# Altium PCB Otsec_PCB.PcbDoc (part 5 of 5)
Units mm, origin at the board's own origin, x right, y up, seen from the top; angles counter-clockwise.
Board outline 170 x 120 mm, 3 copper layers (Top Layer, Internal Plane 1, Bottom Layer), stack 1.608 mm thick; 1624 components, 0 nets, 5478 pads, 0 vias.
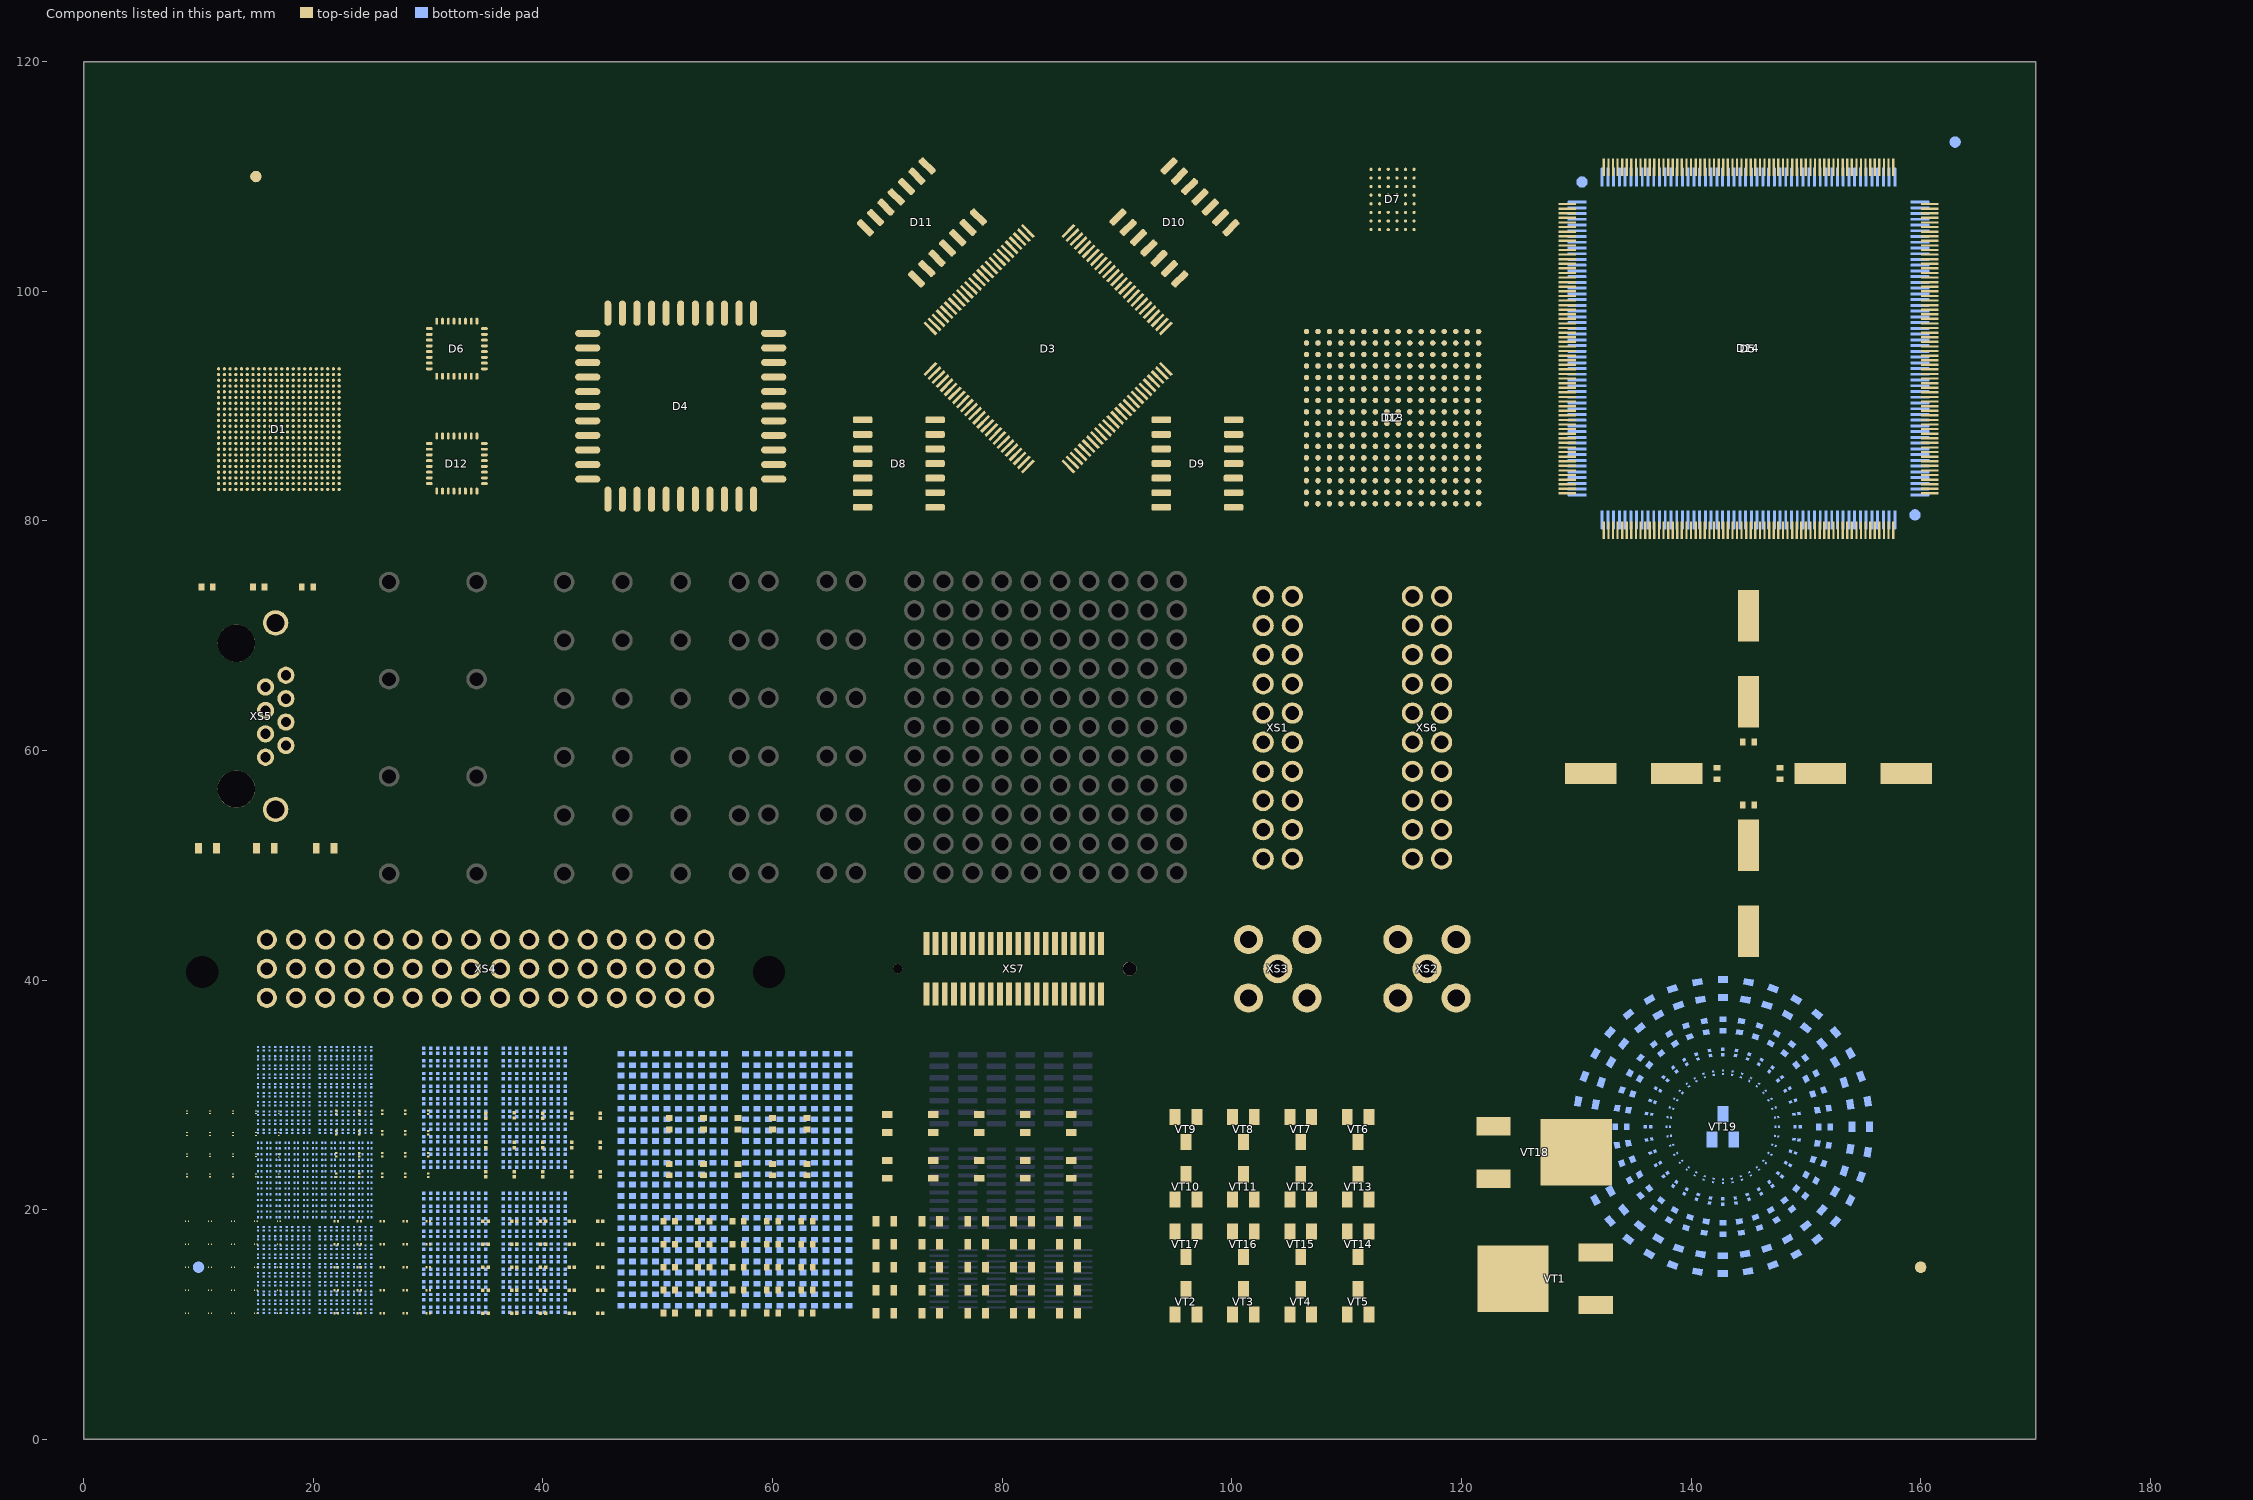
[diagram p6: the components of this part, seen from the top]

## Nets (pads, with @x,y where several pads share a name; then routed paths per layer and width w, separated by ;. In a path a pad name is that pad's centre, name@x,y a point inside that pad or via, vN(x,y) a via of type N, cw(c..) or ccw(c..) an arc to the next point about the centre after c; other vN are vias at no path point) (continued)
copper on no net: | length 2663.3
  Top Layer w0.051: 26.98,107.465 28.149,107.465 ; 26.98,107.516 27.996,107.516 ; 26.98,107.567 27.895,107.567 ; 26.98,107.618 27.793,107.618 ; 26.98,107.668 27.742,107.668 ; 26.98,107.719 27.641,107.719 ; 27.031,107.364 28.453,107.364 ; 27.031,107.414 28.301,107.414 ; 27.031,107.77 27.742,107.77 ; 27.031,107.821 27.844,107.821 ; 27.082,107.262 28.86,107.262 ; 27.082,107.313 28.606,107.313 ; 27.082,107.872 27.945,107.872 ; 27.133,107.211 29.063,107.211 ; 27.133,107.922 28.047,107.922 ; 27.183,107.16 29.317,107.16 ; 27.183,107.973 28.149,107.973 ; 27.234,107.11 30.028,107.11 ; 27.234,108.024 28.301,108.024 ; 27.285,107.059 30.028,107.059 ; 27.336,107.008 30.485,107.008 ; 27.336,108.075 28.453,108.075 ; 27.387,108.126 28.606,108.126 ; 27.437,106.957 31.095,106.957 ; 27.488,106.906 36.48,106.906 ; 27.488,108.176 28.809,108.176 ; 27.59,106.856 36.48,106.856 ; 27.59,108.227 29.012,108.227 ; 27.691,106.805 36.429,106.805 ; 27.742,108.278 29.215,108.278 ; 27.793,106.754 36.429,106.754 ; 27.895,106.703 36.378,106.703 ; 27.895,108.329 29.52,108.329 ; 27.996,106.652 36.327,106.652 ; 28.047,108.38 29.825,108.38 ; 28.149,106.602 36.277,106.602 ; 28.199,108.43 30.181,108.43 ; 28.301,106.551 36.226,106.551 ; 28.453,106.5 36.124,106.5 ; 28.453,108.481 30.689,108.481 ; 28.606,106.449 36.023,106.449 ; 28.657,108.532 31.4,108.532 ; 28.809,106.398 35.921,106.398 ; 28.911,108.583 36.327,108.583 ; 29.012,106.348 35.819,106.348 ; 29.215,106.246 35.464,106.246 ; 29.215,106.297 35.667,106.297 ; 29.215,108.634 36.023,108.634 ; 29.266,106.094 29.723,106.094 ; 29.266,106.144 29.673,106.144 ; 29.266,106.195 29.673,106.195 ; 29.317,105.992 29.774,105.992 ; 29.317,106.043 29.723,106.043 ; 29.368,105.89 29.876,105.89 ; 29.368,105.941 29.825,105.941 ; 29.368,107.16 30.181,107.16 ; 29.419,105.789 29.927,105.789 ; 29.419,105.84 29.876,105.84 ; 29.419,107.211 30.333,107.211 ; 29.469,105.738 29.977,105.738 ; 29.52,105.687 30.028,105.687 ; 29.52,107.262 30.536,107.262 ; 29.571,105.586 30.181,105.586 ; 29.571,105.636 30.13,105.636 ; 29.571,108.684 35.667,108.684 ; 29.622,105.535 30.231,105.535 ; 29.622,107.313 30.739,107.313 ; 29.673,105.484 30.333,105.484 ; 29.723,105.433 30.435,105.433 ; 29.723,107.364 30.993,107.364 ; 29.774,105.382 30.536,105.382 ; 29.825,105.332 30.638,105.332 ; 29.825,106.195 35.21,106.195 ; 29.876,105.281 30.79,105.281 ; 29.876,107.414 31.349,107.414 ; 29.927,105.23 31.4,105.23 ; 30.028,105.179 31.298,105.179 ; 30.028,107.465 31.857,107.465 ; 30.028,108.735 35.21,108.735 ; 30.079,105.128 31.298,105.128 ; 30.13,105.078 31.603,105.078 ; 30.181,106.144 34.956,106.144 ; 30.181,111.275 31.044,111.275 ; 30.181,111.326 30.841,111.326 ; 30.181,111.377 30.587,111.377 ; 30.231,105.027 32.06,105.027 ; 30.231,107.516 35.819,107.516 ; 30.231,111.224 31.197,111.224 ; 30.282,104.976 34.854,104.976 ; 30.282,111.174 31.349,111.174 ; 30.333,111.123 31.501,111.123 ; 30.384,104.925 34.803,104.925 ; 30.435,107.567 35.616,107.567 ; 30.435,111.072 31.603,111.072 ; 30.485,104.874 34.803,104.874 ; 30.485,111.021 31.705,111.021 ; 30.536,108.786 34.702,108.786 ; 30.536,110.97 31.755,110.97 ; 30.587,104.824 34.753,104.824 ; 30.587,110.92 31.857,110.92 ; 30.638,104.773 34.702,104.773 ; 30.638,106.094 34.549,106.094 ; 30.638,107.618 35.413,107.618 ; 30.638,110.869 31.908,110.869 ; 30.739,110.818 31.959,110.818 ; 30.79,104.722 34.651,104.722 ; 30.79,110.767 32.009,110.767 ; 30.841,104.671 34.6,104.671 ; 30.841,110.716 32.06,110.716 ; 30.892,104.57 34.346,104.57 ; 30.892,104.62 34.499,104.62 ; 30.892,105.281 31.552,105.281 ; 30.892,110.666 32.111,110.666 ; 30.943,104.519 34.194,104.519 ; 30.943,107.668 35.057,107.668 ; 30.943,110.615 32.111,110.615 ; 30.993,104.468 31.451,104.468 ; 30.993,105.332 31.654,105.332 ; 31.044,104.417 31.501,104.417 ; 31.044,105.382 31.857,105.382 ; 31.044,110.564 32.162,110.564 ; 31.095,104.366 31.552,104.366 ; 31.095,110.513 32.162,110.513 ; 31.146,104.316 31.654,104.316 ; 31.146,105.433 32.111,105.433 ; 31.146,110.462 32.213,110.462 ; 31.197,104.265 31.705,104.265 ; 31.197,110.412 32.213,110.412 ; 31.247,106.043 34.041,106.043 ; 31.247,110.361 32.263,110.361 ; 31.298,104.214 31.755,104.214 ; 31.298,105.484 34.549,105.484 ; 31.298,107.719 34.651,107.719 ; 31.298,108.837 33.94,108.837 ; 31.298,110.31 32.263,110.31 ; 31.349,104.163 31.857,104.163 ; 31.4,104.112 31.908,104.112 ; 31.4,110.259 32.263,110.259 ; 31.451,105.535 34.448,105.535 ; 31.451,110.208 32.263,110.208 ; 31.501,104.062 31.959,104.062 ; 31.501,110.158 32.314,110.158 ; 31.552,104.011 32.06,104.011 ; 31.552,104.468 34.041,104.468 ; 31.552,110.107 32.314,110.107 ; 31.603,105.586 34.295,105.586 ; 31.603,110.056 32.314,110.056 ; 31.654,103.96 32.111,103.96 ; 31.654,110.005 32.314,110.005 ; 31.705,103.909 32.162,103.909 ; 31.705,109.954 32.314,109.954 ; 31.755,103.858 32.213,103.858 ; 31.755,109.904 32.314,109.904 ; 31.806,104.417 33.737,104.417 ; 31.806,105.636 34.041,105.636 ; 31.806,109.853 32.314,109.853 ; 31.857,103.808 32.263,103.808 ; 31.857,107.77 33.889,107.77 ; 31.857,109.802 32.314,109.802 ; 31.908,103.757 32.314,103.757 ; 31.908,109.751 32.314,109.751 ; 31.959,103.706 32.365,103.706 ; 31.959,109.7 32.365,109.7 ; 32.009,103.655 32.416,103.655 ; 32.009,109.65 32.365,109.65 ; 32.06,103.604 32.721,103.604 ; 32.111,103.554 32.721,103.554 ; 32.111,109.599 32.365,109.599 ; 32.162,103.503 32.721,103.503 ; 32.162,105.687 33.635,105.687 ; 32.162,109.548 32.365,109.548 ; 32.213,103.452 32.721,103.452 ; 32.213,104.366 33.279,104.366 ; 32.213,109.446 32.365,109.446 ; 32.213,109.497 32.365,109.497 ; 32.263,103.401 32.721,103.401 ; 32.263,109.396 32.365,109.396 ; 32.314,103.3 32.721,103.3 ; 32.314,103.35 32.721,103.35 ; 32.365,103.198 32.721,103.198 ; 32.365,103.249 32.721,103.249 ; 32.416,103.046 32.721,103.046 ; 32.416,103.096 32.721,103.096 ; 32.416,103.147 32.721,103.147 ; 32.467,102.842 32.721,102.842 ; 32.467,102.893 32.721,102.893 ; 32.467,102.944 32.721,102.944 ; 32.467,102.995 32.721,102.995 ; 32.467,103.655 32.721,103.655 ; 32.467,103.706 32.721,103.706 ; 32.467,103.757 32.721,103.757 ; 32.467,103.808 32.721,103.808 ; 32.467,103.858 32.721,103.858 ; 32.467,103.909 32.721,103.909 ; 32.467,103.96 32.721,103.96 ; 32.467,104.011 32.721,104.011 ; 32.467,104.062 32.721,104.062 ; 32.467,104.112 32.721,104.112 ; 32.467,104.163 32.721,104.163 ; 32.467,104.214 32.721,104.214 ; 32.467,104.265 32.721,104.265 ; 32.467,104.316 32.721,104.316 ; 32.467,105.027 32.721,105.027 ; 32.467,105.078 32.721,105.078 ; 32.467,105.128 32.721,105.128 ; 32.467,105.179 32.721,105.179 ; 32.467,105.23 32.721,105.23 ; 32.467,105.281 32.721,105.281 ; 32.467,105.332 32.721,105.332 ; 32.467,105.382 32.721,105.382 ; 32.467,105.433 32.721,105.433 ; 32.467,105.738 32.721,105.738 ; 32.467,105.789 32.721,105.789 ; 32.467,105.84 32.721,105.84 ; 32.467,105.89 32.721,105.89 ; 32.467,105.941 32.721,105.941 ; 32.467,105.992 32.721,105.992 ; 32.467,106.957 32.721,106.957 ; 32.467,107.008 32.721,107.008 ; 32.467,107.059 32.721,107.059 ; 32.467,107.11 32.721,107.11 ; 32.467,107.16 32.721,107.16 ; 32.467,107.211 32.721,107.211 ; 32.467,107.262 32.721,107.262 ; 32.467,107.313 32.721,107.313 ; 32.467,107.364 32.721,107.364 ; 32.467,107.414 32.721,107.414 ; 32.467,107.465 32.721,107.465 ; 32.467,107.821 32.721,107.821 ; 32.467,107.872 32.721,107.872 ; 32.467,107.922 32.721,107.922 ; 32.467,107.973 32.721,107.973 ; 32.467,108.024 32.721,108.024 ; 32.467,108.075 32.721,108.075 ; 32.467,108.126 32.721,108.126 ; 32.467,108.176 32.721,108.176 ; 32.467,108.227 32.721,108.227 ; 32.467,108.278 32.721,108.278 ; 32.467,108.329 32.721,108.329 ; 32.467,108.38 32.721,108.38 ; 32.467,108.43 32.721,108.43 ; 32.467,108.481 32.721,108.481 ; 32.467,108.532 32.721,108.532 ; 32.467,108.888 32.771,108.888 ; 32.467,108.938 32.771,108.938 ; 32.467,108.989 32.771,108.989 ; 32.467,109.04 32.771,109.04 ; 32.467,109.091 32.771,109.091 ; 32.467,109.142 32.822,109.142 ; 32.467,109.192 32.822,109.192 ; 32.467,109.243 32.822,109.243 ; 32.467,109.294 32.822,109.294 ; 32.467,109.345 32.873,109.345 ; 32.467,109.396 32.873,109.396 ; 32.467,109.446 32.924,109.446 ; 32.467,109.497 32.924,109.497 ; 32.467,109.548 32.924,109.548 ; 32.467,109.599 32.975,109.599 ; 32.467,109.65 32.975,109.65 ; 32.517,109.7 33.025,109.7 ; 32.517,109.751 33.025,109.751 ; 32.517,109.802 33.076,109.802 ; 32.517,109.853 33.076,109.853 ; 32.517,109.904 33.127,109.904 ; 32.517,109.954 33.127,109.954 ; 32.517,110.005 33.178,110.005 ; 32.517,110.056 33.229,110.056 ; 32.517,110.107 33.229,110.107 ; 32.517,110.158 33.279,110.158 ; 32.568,110.208 33.279,110.208 ; 32.568,110.259 33.33,110.259 ; 32.568,110.31 33.381,110.31 ; 32.568,110.361 33.381,110.361 ; 32.568,110.412 33.432,110.412 ; 32.619,110.462 33.483,110.462 ; 32.619,110.513 33.483,110.513 ; 32.619,110.564 33.533,110.564 ; 32.67,110.615 33.584,110.615 ; 32.67,110.666 33.635,110.666 ; 32.721,110.716 33.635,110.716 ; 32.721,110.767 33.686,110.767 ; 32.721,110.818 33.737,110.818 ; 32.771,110.869 33.787,110.869 ; 32.771,110.92 33.787,110.92 ; 32.822,110.97 33.838,110.97 ; 32.873,111.021 33.889,111.021 ; 32.873,111.072 33.94,111.072 ; 32.924,111.123 33.991,111.123 ; 32.975,111.174 34.041,111.174 ; 33.025,111.224 34.041,111.224 ; 33.025,111.275 34.092,111.275 ; 33.076,111.326 34.143,111.326 ; 33.127,111.377 34.194,111.377 ; 33.178,111.428 34.245,111.428 ; 33.229,111.478 34.295,111.478 ; 33.33,111.529 34.346,111.529 ; 33.381,111.58 34.346,111.58 ; 33.432,105.027 34.854,105.027 ; 33.432,111.631 34.397,111.631 ; 33.483,111.682 34.448,111.682 ; 33.584,105.433 34.651,105.433 ; 33.584,111.732 34.499,111.732 ; 33.635,111.783 34.549,111.783 ; 33.686,111.834 34.6,111.834 ; 33.787,111.885 34.651,111.885 ; 33.838,108.532 36.581,108.532 ; 33.838,111.936 34.702,111.936 ; 33.889,105.078 34.854,105.078 ; 33.94,105.382 34.702,105.382 ; 33.94,111.986 34.753,111.986 ; 34.041,107.465 35.972,107.465 ; 34.041,112.037 34.803,112.037 ; 34.092,105.128 34.854,105.128 ; 34.092,112.088 34.854,112.088 ; 34.143,105.332 34.753,105.332 ; 34.194,106.957 36.48,106.957 ; 34.194,112.139 34.854,112.139 ; 34.295,105.179 34.854,105.179 ; 34.295,105.281 34.803,105.281 ; 34.295,112.19 34.905,112.19 ; 34.397,105.23 34.854,105.23 ; 34.397,112.24 34.956,112.24 ; 34.549,108.481 36.835,108.481 ; 34.549,112.291 34.956,112.291 ; 34.6,107.414 36.124,107.414 ; 34.651,112.342 34.956,112.342 ; 34.753,107.008 36.48,107.008 ; 34.803,112.393 34.956,112.393 ; 34.956,107.364 36.226,107.364 ; 35.057,108.43 37.039,108.43 ; 35.108,107.059 36.48,107.059 ; 35.21,107.313 36.277,107.313 ; 35.362,107.11 36.48,107.11 ; 35.413,107.262 36.327,107.262 ; 35.413,108.38 37.191,108.38 ; 35.515,107.16 36.429,107.16 ; 35.565,107.211 36.378,107.211 ; 35.718,108.329 37.343,108.329 ; 36.023,108.278 37.496,108.278 ; 36.124,103.147 38.715,103.147 ; 36.124,103.198 38.715,103.198 ; 36.124,103.249 37.293,103.249 ; 36.124,103.3 37.191,103.3 ; 36.124,103.35 37.14,103.35 ; 36.124,103.401 37.089,103.401 ; 36.124,103.452 37.039,103.452 ; 36.124,103.503 37.039,103.503 ; 36.124,103.554 37.039,103.554 ; 36.124,103.604 36.988,103.604 ; 36.124,103.655 36.988,103.655 ; 36.124,103.706 36.988,103.706 ; 36.124,103.757 36.988,103.757 ; 36.124,103.808 36.988,103.808 ; 36.124,103.858 36.988,103.858 ; 36.124,103.909 36.988,103.909 ; 36.124,103.96 36.988,103.96 ; 36.124,104.011 36.988,104.011 ; 36.124,104.062 36.988,104.062 ; 36.124,104.112 36.988,104.112 ; 36.124,104.163 36.988,104.163 ; 36.124,104.214 36.988,104.214 ; 36.124,104.265 36.988,104.265 ; 36.124,104.316 36.988,104.316 ; 36.124,104.366 36.988,104.366 ; 36.124,104.417 36.988,104.417 ; 36.124,104.468 36.988,104.468 ; 36.124,104.519 36.988,104.519 ; 36.124,104.57 36.988,104.57 ; 36.124,104.62 37.039,104.62 ; 36.124,104.671 37.039,104.671 ; 36.124,104.722 37.039,104.722 ; 36.124,104.773 37.089,104.773 ; 36.124,104.824 37.14,104.824 ; 36.124,104.874 37.191,104.874 ; 36.124,104.925 37.293,104.925 ; 36.124,104.976 38.715,104.976 ; 36.124,105.027 38.715,105.027 ; 36.175,103.046 38.664,103.046 ; 36.175,103.096 38.664,103.096 ; 36.175,105.078 38.664,105.078 ; 36.175,105.128 38.664,105.128 ; 36.226,102.995 38.613,102.995 ; 36.226,105.179 38.613,105.179 ; 36.226,108.227 37.597,108.227 ; 36.277,102.944 38.563,102.944 ; 36.277,105.23 38.563,105.23 ; 36.327,102.893 38.512,102.893 ; 36.327,105.281 38.512,105.281 ; 36.429,102.842 38.41,102.842 ; 36.429,105.332 38.359,105.332 ; 36.429,108.176 37.75,108.176 ; 36.632,108.126 37.851,108.126 ; 36.785,108.075 37.902,108.075 ; 36.937,106.957 37.851,106.957 ; 36.937,107.008 37.902,107.008 ; 36.937,107.059 37.953,107.059 ; 36.937,107.11 38.004,107.11 ; 36.937,107.16 38.055,107.16 ; 36.937,107.211 38.105,107.211 ; 36.937,108.024 38.004,108.024 ; 36.988,106.805 37.597,106.805 ; 36.988,106.856 37.699,106.856 ; 36.988,106.906 37.75,106.906 ; 36.988,107.262 38.156,107.262 ; 36.988,107.313 38.207,107.313 ; 36.988,107.364 38.207,107.364 ; 37.039,106.703 37.394,106.703 ; 37.039,106.754 37.496,106.754 ; 37.039,107.414 38.207,107.414 ; 37.089,107.465 38.258,107.465 ; 37.089,107.973 38.055,107.973 ; 37.14,106.652 37.242,106.652 ; 37.191,107.516 38.258,107.516 ; 37.191,107.922 38.105,107.922 ; 37.293,107.567 38.258,107.567 ; 37.293,107.872 38.156,107.872 ; 37.394,107.618 38.258,107.618 ; 37.394,107.821 38.207,107.821 ; 37.445,107.668 38.258,107.668 ; 37.496,107.77 38.207,107.77 ; 37.547,103.249 38.715,103.249 ; 37.547,104.925 38.715,104.925 ; 37.547,107.719 38.258,107.719 ; 37.648,103.3 38.715,103.3 ; 37.648,104.874 38.715,104.874 ; 37.699,103.35 38.715,103.35 ; 37.699,104.824 38.715,104.824 ; 37.75,103.401 38.715,103.401 ; 37.75,104.722 38.715,104.722 ; 37.75,104.773 38.715,104.773 ; 37.801,103.452 38.715,103.452 ; 37.801,103.503 38.715,103.503 ; 37.801,103.554 38.715,103.554 ; 37.801,103.604 38.715,103.604 ; 37.801,103.655 38.715,103.655 ; 37.801,103.706 38.715,103.706 ; 37.801,103.757 38.715,103.757 ; 37.801,103.808 38.715,103.808 ; 37.801,103.858 38.715,103.858 ; 37.801,103.909 38.715,103.909 ; 37.801,103.96 38.715,103.96 ; 37.801,104.011 38.715,104.011 ; 37.801,104.062 38.715,104.062 ; 37.801,104.112 38.715,104.112 ; 37.801,104.163 38.715,104.163 ; 37.801,104.214 38.715,104.214 ; 37.801,104.265 38.715,104.265 ; 37.801,104.316 38.715,104.316 ; 37.801,104.366 38.715,104.366 ; 37.801,104.417 38.715,104.417 ; 37.801,104.468 38.715,104.468 ; 37.801,104.519 38.715,104.519 ; 37.801,104.57 38.715,104.57 ; 37.801,104.62 38.715,104.62 ; 37.801,104.671 38.715,104.671 ; 39.477,102.842 41.357,102.842 ; 39.477,102.893 41.458,102.893 ; 39.477,102.944 41.509,102.944 ; 39.477,102.995 41.56,102.995 ; 39.477,103.046 41.611,103.046 ; 39.477,103.096 41.611,103.096 ; 39.477,103.147 41.661,103.147 ; 39.477,103.198 41.661,103.198 ; 39.477,104.265 41.407,104.265 ; 39.477,104.316 40.645,104.316 ; 39.477,104.366 40.544,104.366 ; 39.477,104.417 40.493,104.417 ; 39.477,104.468 40.442,104.468 ; 39.477,104.519 40.442,104.519 ; 39.477,104.57 40.391,104.57 ; 39.477,104.62 40.391,104.62 ; 39.477,104.671 40.391,104.671 ; 39.477,104.722 40.391,104.722 ; 39.477,104.773 40.442,104.773 ; 39.477,104.824 40.493,104.824 ; 39.477,104.874 40.544,104.874 ; 39.477,104.925 40.595,104.925 ; 39.477,104.976 41.661,104.976 ; 39.528,104.112 41.56,104.112 ; 39.528,104.163 41.509,104.163 ; 39.528,104.214 41.458,104.214 ; 39.528,105.027 41.661,105.027 ; 39.528,105.078 41.661,105.078 ; 39.528,105.128 41.661,105.128 ; 39.579,104.062 41.611,104.062 ; 39.579,105.179 41.661,105.179 ; 39.629,104.011 41.611,104.011 ; 39.629,105.23 41.661,105.23 ; 39.68,103.96 41.661,103.96 ; 39.68,105.281 41.661,105.281 ; 39.782,103.909 41.661,103.909 ; 39.833,105.332 41.661,105.332 ; 40.493,103.858 41.661,103.858 ; 40.544,103.249 41.661,103.249 ; 40.645,103.3 41.661,103.3 ; 40.645,103.808 41.661,103.808 ; 40.696,103.35 41.661,103.35 ; 40.696,103.706 41.661,103.706 ; 40.696,103.757 41.661,103.757 ; 40.747,103.401 41.661,103.401 ; 40.747,103.452 41.661,103.452 ; 40.747,103.503 41.661,103.503 ; 40.747,103.554 41.661,103.554 ; 40.747,103.604 41.661,103.604 ; 40.747,103.655 41.661,103.655 ; 42.474,103.147 44.201,103.147 ; 42.474,103.198 44.201,103.198 ; 42.474,103.249 43.592,103.249 ; 42.474,103.3 43.49,103.3 ; 42.474,103.35 43.439,103.35 ; 42.474,103.401 43.439,103.401 ; 42.474,103.452 43.389,103.452 ; 42.474,103.503 43.389,103.503 ; 42.474,103.554 43.389,103.554 ; 42.474,103.604 43.389,103.604 ; 42.474,103.655 43.389,103.655 ; 42.474,103.706 43.389,103.706 ; 42.474,103.757 43.389,103.757 ; 42.474,103.808 43.389,103.808 ; 42.474,103.858 43.389,103.858 ; 42.474,103.909 43.389,103.909 ; 42.474,103.96 43.389,103.96 ; 42.474,104.011 43.389,104.011 ; 42.474,104.062 43.389,104.062 ; 42.474,104.112 43.389,104.112 ; 42.474,104.163 43.389,104.163 ; 42.474,104.214 43.389,104.214 ; 42.474,104.265 43.389,104.265 ; 42.474,104.316 43.389,104.316 ; 42.474,104.366 43.389,104.366 ; 42.474,104.417 43.389,104.417 ; 42.474,104.468 43.389,104.468 ; 42.474,104.519 43.389,104.519 ; 42.474,104.57 43.389,104.57 ; 42.474,104.62 43.389,104.62 ; 42.474,104.671 43.389,104.671 ; 42.474,104.722 43.389,104.722 ; 42.474,104.773 43.389,104.773 ; 42.474,104.824 43.389,104.824 ; 42.474,104.874 43.389,104.874 ; 42.474,104.925 43.389,104.925 ; 42.474,104.976 44.201,104.976 ; 42.474,105.027 44.201,105.027 ; 42.474,105.078 44.201,105.078 ; 42.474,105.128 44.201,105.128 ; 42.474,105.179 44.201,105.179 ; 42.474,105.23 44.201,105.23 ; 42.474,105.281 44.201,105.281 ; 42.474,105.332 44.201,105.332 ; 42.474,105.382 43.389,105.382 ; 42.474,105.433 43.389,105.433 ; 42.474,105.484 43.389,105.484 ; 42.474,105.535 43.389,105.535 ; 42.474,105.586 43.389,105.586 ; 42.474,105.636 43.389,105.636 ; 42.474,105.687 43.389,105.687 ; 42.474,105.738 43.389,105.738 ; 42.474,105.789 43.389,105.789 ; 42.474,105.84 43.389,105.84 ; 42.474,105.89 43.389,105.89 ; 42.474,105.941 43.389,105.941 ; 42.474,105.992 43.389,105.992 ; 42.474,106.043 43.389,106.043 ; 42.525,103.046 44.201,103.046 ; 42.525,103.096 44.201,103.096 ; 42.576,102.995 44.201,102.995 ; 42.627,102.944 44.201,102.944 ; 42.677,102.893 44.201,102.893 ; 42.779,102.842 44.201,102.842 ; 44.963,103.096 47.453,103.096 ; 44.963,103.147 47.453,103.147 ; 44.963,103.198 47.453,103.198 ; 44.963,103.249 46.081,103.249 ; 44.963,103.3 45.979,103.3 ; 44.963,103.35 45.929,103.35 ; 44.963,103.401 45.878,103.401 ; 44.963,103.452 45.878,103.452 ; 44.963,103.503 45.827,103.503 ; 44.963,103.554 45.827,103.554 ; 44.963,103.604 45.827,103.604 ; 44.963,103.655 45.827,103.655 ; 44.963,103.706 47.503,103.706 ; 44.963,103.757 47.503,103.757 ; 44.963,103.808 47.503,103.808 ; 44.963,103.858 47.503,103.858 ; 44.963,103.909 47.503,103.909 ; 44.963,103.96 47.503,103.96 ; 44.963,104.011 47.503,104.011 ; 44.963,104.062 47.503,104.062 ; 44.963,104.112 45.827,104.112 ; 44.963,104.163 45.827,104.163 ; 44.963,104.214 45.827,104.214 ; 44.963,104.265 45.827,104.265 ; 44.963,104.316 45.827,104.316 ; 44.963,104.366 45.827,104.366 ; 44.963,104.417 45.827,104.417 ; 44.963,104.468 45.827,104.468 ; 44.963,104.519 45.827,104.519 ; 44.963,104.57 45.827,104.57 ; 44.963,104.62 45.827,104.62 ; 44.963,104.671 45.878,104.671 ; 44.963,104.722 45.878,104.722 ; 44.963,104.773 45.878,104.773 ; 44.963,104.824 45.929,104.824 ; 44.963,104.874 46.03,104.874 ; 44.963,104.925 46.132,104.925 ; 44.963,104.976 47.503,104.976 ; 44.963,105.027 47.503,105.027 ; 44.963,105.078 47.453,105.078 ; 45.014,102.995 47.453,102.995 ; 45.014,103.046 47.453,103.046 ; 45.014,105.128 47.453,105.128 ; 45.014,105.179 47.402,105.179 ; 45.065,102.944 47.453,102.944 ; 45.065,105.23 47.351,105.23 ; 45.116,102.893 47.453,102.893 ; 45.167,105.281 47.3,105.281 ; 45.268,102.842 47.453,102.842 ; 45.268,105.332 47.199,105.332 ; 46.335,104.925 47.503,104.925 ; 46.437,104.874 47.503,104.874 ; 46.487,104.824 47.503,104.824 ; 46.538,104.773 47.503,104.773 ; 46.589,104.62 47.503,104.62 ; 46.589,104.671 47.503,104.671 ; 46.589,104.722 47.503,104.722 ; 46.64,104.112 47.503,104.112 ; 46.64,104.163 47.503,104.163 ; 46.64,104.214 47.503,104.214 ; 46.64,104.265 47.503,104.265 ; 46.64,104.316 47.503,104.316 ; 46.64,104.366 47.503,104.366 ; 46.64,104.417 47.503,104.417 ; 46.64,104.468 47.503,104.468 ; 46.64,104.519 47.503,104.519 ; 46.64,104.57 47.503,104.57 ; 48.367,103.096 50.755,103.096 ; 48.367,103.147 50.755,103.147 ; 48.367,103.198 50.755,103.198 ; 48.367,103.249 49.485,103.249 ; 48.367,103.3 49.383,103.3 ; 48.367,103.35 49.332,103.35 ; 48.367,103.401 49.281,103.401 ; 48.367,103.452 49.281,103.452 ; 48.367,103.503 49.231,103.503 ; 48.367,103.554 49.231,103.554 ; 48.367,103.604 49.231,103.604 ; 48.367,103.655 49.231,103.655 ; 48.367,103.706 49.231,103.706 ; 48.367,103.757 49.231,103.757 ; 48.367,103.808 49.231,103.808 ; 48.367,103.858 49.231,103.858 ; 48.367,103.909 49.231,103.909 ; 48.367,103.96 49.231,103.96 ; 48.367,104.011 49.231,104.011 ; 48.367,104.062 49.231,104.062 ; 48.367,104.112 49.231,104.112 ; 48.367,104.163 49.231,104.163 ; 48.367,104.214 49.231,104.214 ; 48.367,104.265 49.231,104.265 ; 48.367,104.316 49.231,104.316 ; 48.367,104.366 49.231,104.366 ; 48.367,104.417 49.231,104.417 ; 48.367,104.468 49.231,104.468 ; 48.367,104.519 49.231,104.519 ; 48.367,104.57 49.231,104.57 ; 48.367,104.62 49.231,104.62 ; 48.367,104.671 49.231,104.671 ; 48.367,104.722 49.281,104.722 ; 48.367,104.773 49.281,104.773 ; 48.367,104.824 49.332,104.824 ; 48.367,104.874 49.383,104.874 ; 48.367,104.925 49.485,104.925 ; 48.367,104.976 50.755,104.976 ; 48.367,105.027 50.755,105.027 ; 48.367,105.078 50.755,105.078 ; 48.418,103.046 50.755,103.046 ; 48.418,105.128 50.755,105.128 ; 48.469,102.944 50.755,102.944 ; 48.469,102.995 50.755,102.995 ; 48.469,105.179 50.755,105.179 ; 48.469,105.23 50.755,105.23 ; 48.57,102.893 50.755,102.893 ; 48.57,105.281 50.755,105.281 ; 48.672,102.842 50.755,102.842 ; 48.672,105.332 50.755,105.332
  Top Layer w1: 4,4 166,4 166,116 4,116 4,4
  Bottom Layer w0.15: 97.7,10.6 97.7,34.6 ; 116.7,10.6 ccw(c112.7,14.6) 116.7,18.6 cw(c120.7,22.6) 116.7,26.6 ccw(c112.7,30.6) 116.7,34.6
  Bottom Layer w0.2: 96.7,10.6 96.7,34.6 ; 114.7,10.6 ccw(c110.7,14.6) 114.7,18.6 cw(c118.7,22.6) 114.7,26.6 ccw(c110.7,30.6) 114.7,34.6
  Bottom Layer w0.25: 95.7,10.6 95.7,34.6 ; 112.7,10.6 ccw(c108.7,14.6) 112.7,18.6 cw(c116.7,22.6) 112.7,26.6 ccw(c108.7,30.6) 112.7,34.6
  Bottom Layer w0.3: 94.7,10.6 94.7,34.6 ; 110.7,10.6 ccw(c106.7,14.6) 110.7,18.6 cw(c114.7,22.6) 110.7,26.6 ccw(c106.7,30.6) 110.7,34.6 ; 126.067,27.233 129.067,27.233 ; 126.317,24.383 129.267,24.883 ; 126.317,30.133 129.267,29.608 ; 127.067,21.558 129.892,22.583 ; 127.067,32.958 129.892,31.933 ; 128.292,18.908 130.892,20.408 ; 128.292,35.583 130.892,34.083 ; 129.967,16.508 132.267,18.433 ; 129.967,37.983 132.267,36.033 ; 132.017,14.458 133.942,16.733 ; 132.042,40.033 133.967,37.733 ; 134.417,12.783 135.917,15.383 ; 134.417,41.708 135.917,39.108 ; 137.042,42.933 138.067,40.108 ; 137.067,11.533 138.092,14.358 ; 139.867,10.783 140.392,13.733 ; 139.867,43.683 140.392,40.708 ; 142.767,10.533 142.767,13.533 ; 142.767,40.933 142.767,43.933 ; 145.117,13.733 145.642,10.783 ; 145.142,40.733 145.667,43.683 ; 147.442,14.358 148.467,11.533 ; 147.442,40.108 148.467,42.933 ; 149.617,15.358 151.092,12.783 ; 149.617,39.083 151.117,41.708 ; 151.567,16.733 153.517,14.433 ; 151.567,37.733 153.492,40.033 ; 153.267,18.433 155.567,16.508 ; 153.267,36.033 155.567,37.958 ; 154.617,34.083 157.217,35.583 ; 154.642,20.383 157.242,18.883 ; 155.642,22.558 158.467,21.533 ; 155.642,31.908 158.442,32.933 ; 156.267,24.883 159.217,24.358 ; 156.267,29.608 159.217,30.133 ; 156.467,27.233 159.467,27.233
  Bottom Layer w0.35: 93.7,10.6 93.7,34.6 ; 108.7,10.6 ccw(c104.7,14.6) 108.7,18.6 cw(c112.7,22.6) 108.7,26.6 ccw(c104.7,30.6) 108.7,34.6
  Bottom Layer w0.4: 92.7,10.6 92.7,34.6 ; 106.7,10.6 ccw(c102.7,14.6) 106.7,18.6 cw(c110.7,22.6) 106.7,26.6 ccw(c102.7,30.6) 106.7,34.6
  Bottom Layer w0.45: 91.7,10.6 91.7,34.6 ; 104.7,10.6 ccw(c100.7,14.6) 104.7,18.6 cw(c108.7,22.6) 104.7,26.6 ccw(c100.7,30.6) 104.7,34.6
  Bottom Layer w0.5: 90.7,10.6 90.7,34.6 ; 102.7,10.6 ccw(c98.7,14.6) 102.7,18.6 cw(c106.7,22.6) 102.7,26.6 ccw(c98.7,30.6) 102.7,34.6 ; 148.267,27.233 ccw(c142.767,27.233) 148.267,27.233 ; 150.267,27.233 ccw(c142.767,27.233) 150.267,27.233 ; 152.967,27.233 ccw(c142.767,27.233) 152.967,27.233
  Bottom Layer w1: 4,4 4,116 166,116 166,4 4,4

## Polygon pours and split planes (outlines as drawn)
no net on Internal Plane 1 (split plane): 9.604,114.925 9.604,114.722 9.604,114.519 9.604,114.315 9.604,114.112 8.588,114.112 8.588,114.315 8.588,114.519 8.588,114.722 8.588,114.925 8.588,115.128 9.604,115.128
no net on Internal Plane 1 (split plane): 6.963,114.519 6.76,114.519 6.76,114.722 6.963,114.722
no net on Internal Plane 1 (split plane): 6.15,113.299 6.353,113.299 6.353,113.096 6.353,112.893 5.947,112.893 5.947,113.096 5.744,113.096 5.744,113.299 5.947,113.299 5.947,113.096 6.15,113.096 6.15,113.299 5.947,113.299 5.947,113.503 6.15,113.503
no net on Internal Plane 1 (split plane): 8.792,111.674 8.792,111.471 8.792,111.267 8.182,111.267 8.182,111.471 8.182,111.674 8.182,111.877 8.792,111.877
no net on Internal Plane 1 (split plane): 9.198,111.674 9.198,111.471 9.401,111.471 9.401,111.267 9.198,111.267 9.198,111.471 8.995,111.471 8.995,111.674 8.995,111.877 9.198,111.877
no net on Internal Plane 1 (split plane): 5.947,112.69 6.556,112.69 6.556,112.487 6.353,112.487 6.353,112.283 6.15,112.283 6.15,112.487 5.744,112.487 5.744,112.69 5.744,112.893 5.947,112.893
no net on Internal Plane 1 (split plane): 5.947,114.925 5.947,114.722 5.947,114.519 5.947,114.315 5.947,114.112 4.931,114.112 4.931,114.315 4.931,114.519 4.931,114.722 4.931,114.925 4.931,115.128 5.947,115.128
no net on Internal Plane 1 (split plane): 5.54,112.893 5.337,112.893 5.337,113.096 5.54,113.096
no net on Internal Plane 1 (split plane): 5.134,113.299 4.931,113.299 4.931,113.503 5.134,113.503
no net on Internal Plane 1 (split plane): 169.49,0.51 0.51,0.51 0.51,119.49 169.49,119.49
no net on Internal Plane 1 (split plane): 5.947,111.267 5.947,111.064 5.947,110.861 5.947,110.658 5.947,110.455 4.931,110.455 4.931,110.658 4.931,110.861 4.931,111.064 4.931,111.267 4.931,111.471 5.947,111.471

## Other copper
Top Layer:
  text "BGA484 (0.5mm)" at 10.75,77.5 h2
  text "QFN32 / 5×5mm" at 30.25,77.5 h2
  text "PLCC44 (1.27mm)" at 45.25,77.5 h2
  text "QFP100 / (0.5mm) / 45° rotate" at 79.5,77.5 h2
  text "SO14" at 95.25,77.5 h2
  text "BGA256 (1.0mm)" at 107.675,77.5 h2
  text "QFP256 (0.4mm)" at 138.7,76.2 h2
  text "PLD-20 (2.54mm)" at 104,47 h2
  text "ALUCAP – C" at 140.475,39.65 h2
  text "DIN41612 16×3 TYPE B" at 25.75,33.5 h2
  text "PL40 (0.8mm)" at 75.75,33.5 h2
  text "UHF Connector" at 104.5,33.5 h2
  text "03015" at 10.75,7.5 h2
  text "01005\"" at 23.5,7.5 h2
  text "0201\"" at 38,7.5 h2
  text "0402\"" at 55,7.5 h2
  text "0603\"" at 76,7.5 h2
  text "SOT23" at 101,7.5 h2
  text "DPAK (TO-252)" at 121.5,7.5 h2
Bottom Layer:
  rectangle: 5,79.25 101.8,115
  text "AREA FOR DISPENSING TESTS" at 101.8,77.5 h2
  text "BGA256 (1.0mm)" at 120.3,77.5 h2
  text "QFP208 (0.5mm)" at 151.3,77.5 h2
  text "100°" at 139.6,47.825 h2 r100
  text "90°" at 143.225,47.15 h2 r90
  text "110°" at 136.05,46.95 h2 r110
  text "80°" at 146.675,46.775 h2 r80
  text "70°" at 150,45.8 h2 r70
  text "120°" at 132.75,45.525 h2 r120
  text "60°" at 153.125,44.25 h2 r60
  text "130°" at 129.725,43.5 h2 r130
  text "50°" at 155.925,42.225 h2 r50
  text "140°" at 127.075,40.975 h2 r140
  text "40°" at 158.35,39.725 h2 r40
  text "150°" at 124.95,38.05 h2 r150
  text "30°" at 160.275,36.8 h2 r30
  text "160°" at 123.35,34.8 h2 r160
  text "20°" at 161.65,33.65 h2 r20
  text "170°" at 122.325,31.275 h2 r170
  text "10°" at 162.45,30.225 h2 r10
  text "180°" at 121.925,27.675 h2 r180
  text "0°" at 161.775,26.775 h2
  text "190°" at 122.15,24.1 h2 r190
  text "350°" at 163.225,23.2 h2 r350
  text "200°" at 123,20.55 h2 r200
  text "340°" at 162.225,19.675 h2 r340
  text "210°" at 124.45,17.225 h2 r210
  text "330°" at 160.6,16.4 h2 r330
  text "D" at 162.725,14.95 h2 r57.68
  text "220°" at 126.475,14.2 h2 r220
  text "I" at 162.175,14.075 h2 r55.18
  text "320°" at 158.45,13.45 h2 r320
  text "S" at 161.6,13.25 h2 r52.93
  text "P" at 160.925,12.425 h2 r50.33
  text "E" at 160.3,11.7 h2 r48.09
  text "230°" at 129,11.575 h2 r230
  text "S" at 162.275,11.3 h2 r49.09
  text "310°" at 155.85,10.975 h2 r310
  text "N" at 159.575,10.9 h2 r45
  text "T" at 161.65,10.55 h2 r47.66
  text "S" at 158.875,10.2 h2 r42.88
  text "A" at 160.825,9.7 h2 r44.36
  text "I" at 158.1,9.5 h2 r40.18
  text "240°" at 131.95,9.4 h2 r240
  text "300°" at 152.8,8.925 h2 r300
  text "N" at 157.325,8.875 h2 r37.63
  text "R" at 160,8.85 h2 r42.46
  text "G" at 156.525,8.25 h2 r34.99
  text "DOTS DISPENSING TESTS" at 65,8 h2
  text "LINES DISPENSING TESTS" at 118,8 h2
  text "250°" at 135.225,7.8 h2 r250
  text "290°" at 149.45,7.475 h2 r290
  text "260°" at 138.7,6.775 h2 r260
  text "280°" at 145.9,6.625 h2 r280
  text "270°" at 142.325,6.375 h2 r270
Internal Plane 1 (plane layer: these items are gaps in the copper):
  rectangle: 6.35,33.375 66.25,47.65
  rectangle: 6.35,47.3 24.475,75.975
  rectangle: 97.975,33.4 110.2,75.9
  rectangle: 24.35,33.4 98.025,60.625
  pour cut-out: 89.825,42.55 89.825,39.775 92.325,39.775 92.325,39.9 92.25,39.825 89.5,39.825
  region: 7.369,112.69 7.166,112.69 7.166,112.487 6.963,112.487 6.963,112.69 6.963,112.893 7.369,112.893
  region: 4.931,112.69 4.931,112.487 4.931,112.283 4.931,112.08 4.931,111.877 4.728,111.877 4.728,112.08 4.728,112.283 4.728,112.487 4.728,112.69 4.728,112.893 4.931,112.893
  region: 7.776,115.128 7.776,114.925 7.979,114.925 7.979,114.722 8.182,114.722 8.182,114.519 8.182,114.315 7.979,114.315 7.979,114.519 7.979,114.722 7.776,114.722 7.776,114.925 7.369,114.925 7.369,115.128 7.572,115.128 7.572,115.331 7.776,115.331
  region: 9.401,114.722 9.401,114.519 9.401,114.315 8.792,114.315 8.792,114.519 8.792,114.722 8.792,114.925 9.401,114.925
  region: 5.744,111.064 5.744,110.861 5.744,110.658 5.134,110.658 5.134,110.861 5.134,111.064 5.134,111.267 5.744,111.267
  region: 5.744,114.722 5.744,114.519 5.744,114.315 5.134,114.315 5.134,114.519 5.134,114.722 5.134,114.925 5.744,114.925
  region: 6.963,114.722 7.572,114.722 7.572,114.519 7.776,114.519 7.776,114.315 7.776,114.112 7.776,113.909 7.979,113.909 7.979,113.706 8.182,113.706 8.182,113.503 7.979,113.503 7.979,113.706 7.776,113.706 7.776,113.909 7.572,113.909 7.572,114.112 7.572,114.315 7.572,114.519 7.166,114.519 7.166,114.315 6.76,114.315 6.76,114.112 6.963,114.112 6.963,113.909 6.76,113.909 6.76,114.112 6.556,114.112 6.556,114.315 6.353,114.315 6.353,114.519 6.353,114.722 6.556,114.722 6.556,114.925 6.963,114.925 hole: 6.963,114.722 6.76,114.722 6.76,114.519 6.963,114.519
  region: 6.15,115.128 6.15,114.925 6.15,114.722 6.15,114.519 6.15,114.315 6.15,114.112 6.15,113.909 4.728,113.909 4.728,114.112 4.728,114.315 4.728,114.519 4.728,114.722 4.728,114.925 4.728,115.128 4.728,115.331 6.15,115.331 hole: 5.947,115.128 4.931,115.128 4.931,114.925 4.931,114.722 4.931,114.519 4.931,114.315 4.931,114.112 5.947,114.112 5.947,114.315 5.947,114.519 5.947,114.722 5.947,114.925
  region: 9.808,115.128 9.808,114.925 9.808,114.722 9.808,114.519 9.808,114.315 9.808,114.112 9.808,113.909 8.385,113.909 8.385,114.112 8.385,114.315 8.385,114.519 8.385,114.722 8.385,114.925 8.385,115.128 8.385,115.331 9.808,115.331 hole: 9.604,115.128 8.588,115.128 8.588,114.925 8.588,114.722 8.588,114.519 8.588,114.315 8.588,114.112 9.604,114.112 9.604,114.315 9.604,114.519 9.604,114.722 9.604,114.925
  region: 6.15,111.471 6.15,111.267 6.15,111.064 6.15,110.861 6.15,110.658 6.15,110.455 6.15,110.251 4.728,110.251 4.728,110.455 4.728,110.658 4.728,110.861 4.728,111.064 4.728,111.267 4.728,111.471 4.728,111.674 6.15,111.674 hole: 5.947,111.471 4.931,111.471 4.931,111.267 4.931,111.064 4.931,110.861 4.931,110.658 4.931,110.455 5.947,110.455 5.947,110.658 5.947,110.861 5.947,111.064 5.947,111.267
  region: 6.353,113.503 6.353,113.299 6.556,113.299 6.556,113.096 6.76,113.096 6.76,112.893 6.76,112.69 6.76,112.487 6.76,112.283 6.963,112.283 6.963,112.08 6.76,112.08 6.76,112.283 6.556,112.283 6.556,112.08 6.76,112.08 6.76,111.877 7.166,111.877 7.166,111.674 7.369,111.674 7.369,111.471 6.963,111.471 6.963,111.267 7.572,111.267 7.572,111.064 7.776,111.064 7.776,110.861 7.979,110.861 7.979,110.658 8.182,110.658 8.182,110.455 8.182,110.251 7.776,110.251 7.776,110.455 7.979,110.455 7.979,110.658 7.776,110.658 7.776,110.861 7.572,110.861 7.572,111.064 7.166,111.064 7.166,110.861 7.369,110.861 7.369,110.658 7.166,110.658 7.166,110.861 6.76,110.861 6.76,110.658 7.166,110.658 7.166,110.455 7.166,110.251 6.76,110.251 6.76,110.455 6.556,110.455 6.556,110.251 6.353,110.251 6.353,110.455 6.353,110.658 6.556,110.658 6.556,110.861 6.556,111.064 6.556,111.267 6.353,111.267 6.353,111.471 6.353,111.674 6.353,111.877 6.353,112.08 6.15,112.08 6.15,112.283 5.947,112.283 5.947,112.08 6.15,112.08 6.15,111.877 5.744,111.877 5.744,112.08 5.744,112.283 5.134,112.283 5.134,112.487 5.54,112.487 5.54,112.69 5.337,112.69 5.337,112.893 5.134,112.893 5.134,113.096 4.728,113.096 4.728,113.299 4.728,113.503 4.728,113.706 5.134,113.706 5.134,113.503 5.744,113.503 5.744,113.706 6.353,113.706 hole: 5.134,113.503 4.931,113.503 4.931,113.299 5.134,113.299 hole: 6.15,113.503 5.947,113.503 5.947,113.299 6.15,113.299 6.15,113.096 5.947,113.096 5.947,113.299 5.744,113.299 5.744,113.096 5.947,113.096 5.947,112.893 6.353,112.893 6.353,113.096 6.353,113.299 6.15,113.299 hole: 5.54,113.096 5.337,113.096 5.337,112.893 5.54,112.893 hole: 5.947,112.893 5.744,112.893 5.744,112.69 5.744,112.487 6.15,112.487 6.15,112.283 6.353,112.283 6.353,112.487 6.556,112.487 6.556,112.69 5.947,112.69
  region: 152 vertices and 2 holes, not listed, extent 6.556,110.251 9.808,114.112
  text "creating / the future" at 52.2,102.75 h2.5
  text "Тайное /  / становится /  / явным" at 107.875,84.05 h3

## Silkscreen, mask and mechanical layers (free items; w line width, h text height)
Top Overlay:
  rectangle: 135,10 155,37.75
Bottom Overlay:
  circle w0.2: c142.775,27.25 r21.4
  rectangle: 124.125,50.525 161.125,73.525
  region: 160.981,108.594 158.619,110.956 160.981,110.956
  lines w0.05: 185.05,102.7 185.05,102.7 ; 185.05,102.7 185.05,102.7
  lines w0.2: 14,7 67.8,7 67.8,35 14,35 14,7 ; 72,7 72,35 119.25,35 119.25,7 72,7
Top Solder:
  text "BGA484 (0.5mm)" at 10.75,77.5 h2
  text "QFN32 / 5×5mm" at 30.25,77.5 h2
  text "PLCC44 (1.27mm)" at 45.25,77.5 h2
  text "QFP100 / (0.5mm) / 45° rotate" at 79.5,77.5 h2
  text "SO14" at 95.25,77.5 h2
  text "BGA256 (1.0mm)" at 107.675,77.5 h2
  text "QFP256 (0.4mm)" at 138.7,76.2 h2
  text "PLD-20 (2.54mm)" at 104,47 h2
  text "ALUCAP – C" at 140.475,39.65 h2
  text "DIN41612 16×3 TYPE B" at 25.75,33.5 h2
  text "PL40 (0.8mm)" at 75.75,33.5 h2
  text "UHF Connector" at 104.5,33.5 h2
  text "03015" at 10.75,7.5 h2
  text "01005\"" at 23.5,7.5 h2
  text "0201\"" at 38,7.5 h2
  text "0402\"" at 55,7.5 h2
  text "0603\"" at 76,7.5 h2
  text "SOT23" at 101,7.5 h2
  text "DPAK (TO-252)" at 121.5,7.5 h2
Bottom Solder:
  text "AREA FOR DISPENSING TESTS" at 101.8,77.5 h2
  text "BGA256 (1.0mm)" at 120.3,77.5 h2
  text "QFP208 (0.5mm)" at 151.3,77.5 h2
  text "100°" at 139.6,47.825 h2 r100
  text "90°" at 143.225,47.15 h2 r90
  text "110°" at 136.05,46.95 h2 r110
  text "80°" at 146.675,46.775 h2 r80
  text "70°" at 150,45.8 h2 r70
  text "120°" at 132.75,45.525 h2 r120
  text "60°" at 153.125,44.25 h2 r60
  text "130°" at 129.725,43.5 h2 r130
  text "50°" at 155.925,42.225 h2 r50
  text "140°" at 127.075,40.975 h2 r140
  text "40°" at 158.35,39.725 h2 r40
  text "150°" at 124.95,38.05 h2 r150
  text "30°" at 160.275,36.8 h2 r30
  text "160°" at 123.35,34.8 h2 r160
  text "20°" at 161.65,33.65 h2 r20
  text "170°" at 122.325,31.275 h2 r170
  text "10°" at 162.45,30.225 h2 r10
  text "180°" at 121.925,27.675 h2 r180
  text "0°" at 161.775,26.775 h2
  text "0°" at 161.775,26.775 h2
  text "190°" at 122.15,24.1 h2 r190
  text "350°" at 163.225,23.2 h2 r350
  text "200°" at 123,20.55 h2 r200
  text "340°" at 162.225,19.675 h2 r340
  text "210°" at 124.45,17.225 h2 r210
  text "330°" at 160.6,16.4 h2 r330
  text "D" at 162.725,14.95 h2 r57.68
  text "220°" at 126.475,14.2 h2 r220
  text "I" at 162.175,14.075 h2 r55.18
  text "320°" at 158.45,13.45 h2 r320
  text "S" at 161.6,13.25 h2 r52.93
  text "P" at 160.925,12.425 h2 r50.33
  text "E" at 160.3,11.7 h2 r48.09
  text "230°" at 129,11.575 h2 r230
  text "S" at 162.275,11.3 h2 r49.09
  text "310°" at 155.85,10.975 h2 r310
  text "N" at 159.575,10.9 h2 r45
  text "T" at 161.65,10.55 h2 r47.66
  text "S" at 158.875,10.2 h2 r42.88
  text "A" at 160.825,9.7 h2 r44.36
  text "I" at 158.1,9.5 h2 r40.18
  text "240°" at 131.95,9.4 h2 r240
  text "300°" at 152.8,8.925 h2 r300
  text "N" at 157.325,8.875 h2 r37.63
  text "R" at 160,8.85 h2 r42.46
  text "G" at 156.525,8.25 h2 r34.99
  text "DOTS DISPENSING TESTS" at 65,8 h2
  text "LINES DISPENSING TESTS" at 118,8 h2
  text "250°" at 135.225,7.8 h2 r250
  text "290°" at 149.45,7.475 h2 r290
  text "260°" at 138.7,6.775 h2 r260
  text "280°" at 145.9,6.625 h2 r280
  text "270°" at 142.325,6.375 h2 r270
Mechanical 15:
  the board outline again, w0.5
